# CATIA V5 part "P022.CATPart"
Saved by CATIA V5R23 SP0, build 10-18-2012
Part number: 05-LICP-T02-E-S07-P022
Definition: Embrayage Mobile
Description: Embrayage Mobile
Bounding box of the stored display mesh (mm): x -8 to 0, y -39.998 to 39.998, z -39.998 to 39.998
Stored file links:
  C:\wamp\www\COURS\CONCEPTION GMP1\TITRE 02-SEMESTRE 2\03-TP7-PRESSE MECANIQUE\eleve\P022.CATPart
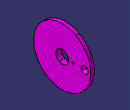
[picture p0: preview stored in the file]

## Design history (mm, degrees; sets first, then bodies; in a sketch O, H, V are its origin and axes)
Body1 (main body)
  Sketch1 on zx-plane, origin (0, 0, 0), H (-1, 0, 0), V (0, 0, 1)
    line L1 (0, 9) -> (0, 40)
    line L2 (0, 40) -> (5, 40)
    line L3 (5, 40) -> (5, 18)
    line L4 (5, 18) -> (8, 18)
    line L5 (8, 18) -> (8, 9)
    line L6 (0, 9) -> (8, 9)
    distance L2 H = 40
    distance L6 H = 9
    distance L5 L1 = 8
    distance L1 L3 = 5
    distance L4 L6 = 9
    vertical: L1 V, L3 V, L5 V
    horizontal: L2 H, L4 H, L6 H
    coincidence: L1 V
  Shaft1: profile Sketch1, axis Sketch1.H, angle 360
  Sketch2 on xy-plane, origin (0, 0, 0), H (1, 0, 0), V (0, 1, 0)
    axis line L1 (-18.2096, 31.5) -> (16.8134, 31.5)
    line L2 (-6.3433, 33) -> (-3.5, 33)
    point P4 (-3.5, 33)
    line L3 (-3.5, 33) -> (0, 36.5)
    point P5 (0, 36.5)
    point P6 (-6.3433, 31.5)
    line L4 (-6.3433, 31.5) -> (-6.3433, 33)
    reference projected line E1 (0, 40) -> (0, -40) from edge [face of Shaft1 | face of Shaft1]
    line L5 (-6.3433, 31.5) -> (0, 31.5)
    point P7 (-6.3433, 31.5)
    line L6 (0, 36.5) -> (0, 31.5)
    reference projected line E2 (-5, 40) -> (-5, -40) from edge [face of Shaft1 | face of Shaft1]
    distance L1 H = 31.5
    length L4 = 1.5
    distance P4 E2 = 1.5
    angle L3 L5 = 45
    horizontal: L1 H, L2 H, L5 H
    vertical: L4 V, L6 V
    coincidence: P5 E1, L5 L1, P6 L1, P6 P7
  Groove1: profile Sketch2, axis Sketch2.L1, angle 360
  Sketch3 on face of Shaft1, origin (0, 16.9645, -4.3678), H (0, 1, 0), V (0, 0, 1)
    point P1 (-1.9645, 4.3678)
    reference intersected line E1 through (0, 4.3678) direction (-1, 0) from xy-plane
    reference intersected line E2 through (-16.9645, 0) direction (0, 1) from zx-plane
    distance E2 P1 = 15
    coincidence: E1 P1
  Hole1: placed by Sketch3, at (0, 15, 0) direction (-1, 0, 0), diameter 3.242, depth 10, threaded "M4", thread diameter 4, thread depth 10, pitch 0.7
